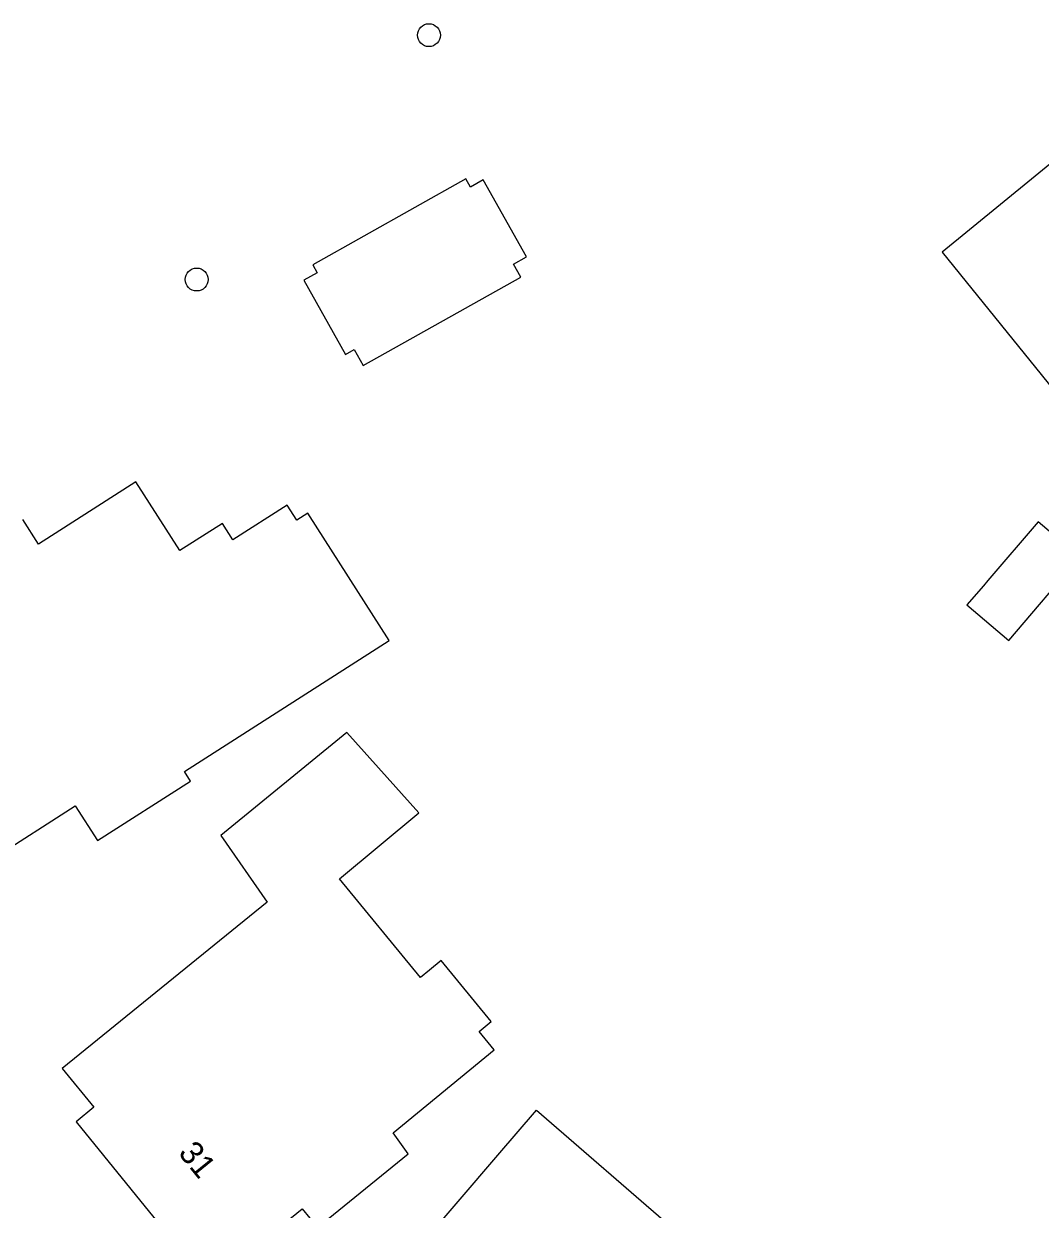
# Model space of a CAD drawing. Extents: x 161354 to 161876, y 382161 to 382804.
# Drawn here: x 161680.9 to 161724.3, y 382336.2 to 382386.9 of the extents above; entities that cross this region are included whole.
import ezdxf

# ---------------------------------------------------------------- set-up
doc = ezdxf.new("R2010")
doc.units = 0
for name, color, linetype in [('IMGEO_Boom', 7, 'Continuous'), ('IMGEO_Pand', 7, 'Continuous'), ('IMGEO_Pand_nummerreeks', 7, 'Continuous')]:
    doc.layers.add(name, color=color, linetype=linetype)

msp = doc.modelspace()

# ---------------------------------------------------------------- linework, layer by layer
at = {"layer": 'IMGEO_Boom'}
for centre in [(161698.181, 382386.422), (161688.251, 382375.969)]:
    msp.add_circle(centre, 0.489, dxfattribs=at)
at = {"layer": 'IMGEO_Pand'}
for points in [[(161726.893, 382368.765), (161732.592, 382375.163), (161726.601, 382382.425), (161720.13, 382377.133), (161726.893, 382368.765)], [(161693.21, 382376.603), (161693.404, 382376.259), (161692.832, 382375.938), (161694.61, 382372.767), (161694.978, 382372.974), (161695.364, 382372.286), (161702.108, 382376.068), (161701.795, 382376.626), (161702.346, 382376.936), (161700.5, 382380.229), (161699.956, 382379.919), (161699.757, 382380.273), (161693.21, 382376.603)], [(161696.484, 382360.535), (161693.005, 382365.975), (161692.537, 382365.676), (161692.122, 382366.324), (161689.802, 382364.841), (161689.355, 382365.54), (161687.532, 382364.375), (161685.652, 382367.318), (161681.483, 382364.651), (161680.81, 382365.704)], [(161721.188, 382362.051), (161722.972, 382360.526), (161726.015, 382364.086), (161724.231, 382365.611), (161722.084, 382363.099), (161721.889, 382362.87), (161721.188, 382362.051)], [(161679.491, 382351.181), (161683.051, 382353.458), (161684.004, 382351.967), (161687.988, 382354.516), (161687.724, 382354.929), (161696.484, 382360.535)], [(161689.288, 382352.192), (161691.267, 382349.342), (161682.503, 382342.228), (161683.854, 382340.562), (161683.091, 382339.943), (161688.753, 382332.965), (161692.759, 382336.218), (161693.41, 382335.415), (161697.292, 382338.567), (161696.655, 382339.476), (161700.969, 382343.026), (161700.325, 382343.81), (161700.84, 382344.233), (161698.7, 382346.834), (161698.203, 382346.426), (161697.822, 382346.113), (161694.352, 382350.333), (161697.755, 382353.161), (161694.67, 382356.587), (161689.288, 382352.192)], [(161697.801, 382319.966), (161695.49, 382321.644), (161695.317, 382322.735), (161693.197, 382324.274), (161696.924, 382329.406), (161697.426, 382329.042), (161700.071, 382332.684), (161697.644, 382334.447), (161701.127, 382338.509), (161702.784, 382340.442), (161708.643, 382335.359), (161707.512, 382333.942), (161707.794, 382333.736)]]:
    msp.add_lwpolyline(points, dxfattribs=at)

# ---------------------------------------------------------------- texts
at = {"layer": 'IMGEO_Pand_nummerreeks'}
msp.add_text('31', height=1, rotation=309.0583, dxfattribs=at).set_placement((161687.429, 382338.596))

doc.saveas('drawing.dxf')
